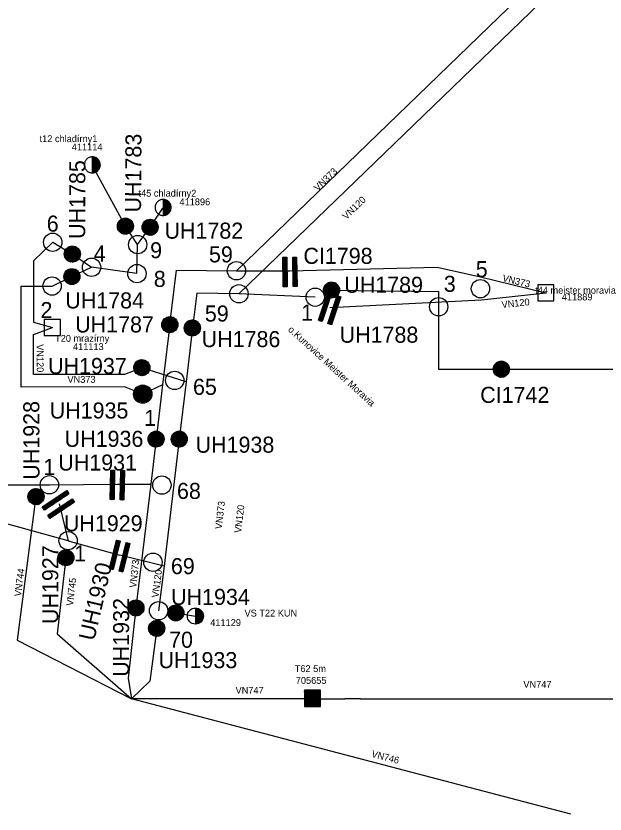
# Model space of a CAD drawing. Extents: x -541380 to -536551, y -1184364 to -1179471.
# Drawn here: x -540352 to -539067, y -1184364 to -1182623 of the extents above; entities that cross this region are included whole.
import ezdxf

# ---------------------------------------------------------------- set-up
doc = ezdxf.new("R2010")
doc.units = 0
for name, color, linetype in [('Default', 7, 'Continuous'), ('Vrstva 1', 7, 'Continuous'), ('Vrstva 2', 7, 'Continuous'), ('Vrstva 20', 7, 'Continuous'), ('Vrstva 3', 7, 'Continuous'), ('Vrstva 5', 7, 'Continuous')]:
    doc.layers.add(name, color=color, linetype=linetype)

# ---------------------------------------------------------------- blocks, each defined once
blk = doc.blocks.new('PS100')
at = {"layer": 'Default'}
for p, q in [((-17.5, -0.7), (0.7, 17.5)), ((-17.5, 0.7), (-0.7, 17.5)), ((-17.4, -2), (2, 17.4)), ((-17.3, 2.2), (-2.2, 17.3)), ((-17.2, -3.3), (3.3, 17.2)), ((-17, 4), (-4, 17)), ((-16.9, -4.4), (4.4, 16.9)), ((-16.6, -5.5), (5.5, 16.6)), ((-16.4, 6), (-6, 16.4)), ((-16.2, -6.5), (6.5, 16.2)), ((-15.8, -7.5), (7.5, 15.8)), ((-15.3, -8.4), (8.4, 15.3)), ((-15.2, 8.6), (-8.6, 15.2)), ((-14.8, -9.3), (9.3, 14.8)), ((-14.2, -10.2), (10.2, 14.2)), ((-13.6, -11), (11, 13.6)), ((-13, -11.7), (11.7, 13)), ((-12.3, -12.5), (12.5, 12.3)), ((-11.5, -13.2), (13.2, 11.5)), ((-10.8, -13.8), (13.8, 10.8)), ((-9.9, -14.4), (14.4, 9.9)), ((-9.1, -14.9), (14.9, 9.1)), ((-8.2, -15.5), (15.5, 8.2)), ((-7.2, -15.9), (15.9, 7.2)), ((-6.2, -16.3), (16.3, 6.2)), ((-5.2, -16.7), (16.7, 5.2)), ((-4.1, -17), (17, 4.1)), ((-2.9, -17.2), (17.2, 2.9)), ((-1.6, -17.4), (17.4, 1.6)), ((-0.3, -17.5), (17.5, 0.3)), ((1.1, -17.4), (17.4, -1.1)), ((2.7, -17.3), (17.3, -2.7)), ((4.5, -16.9), (16.9, -4.5)), ((6.7, -16.2), (16.2, -6.7)), ((9.7, -14.5), (14.5, -9.7))]:
    blk.add_line(p, q, dxfattribs=at)
blk.add_circle((0, 0), 17.5, dxfattribs=at)
blk = doc.blocks.new('PS140')
at = {"layer": 'Default'}
for p, q in [((-17.5, 0), (0, 17.5)), ((-17.4, -1.4), (1.4, 17.4)), ((-17.4, 1.5), (-1.5, 17.4)), ((-17.3, -2.6), (2.6, 17.3)), ((-17.2, 3.1), (-3.1, 17.2)), ((-17.1, -3.8), (3.8, 17.1)), ((-16.8, -4.9), (4.9, 16.8)), ((-16.8, 5), (-5, 16.8)), ((-16.4, -6), (6, 16.4)), ((-16, -7), (7, 16)), ((-15.9, 7.2), (-7.2, 15.9)), ((-15.6, -8), (8, 15.6)), ((-15.1, -8.9), (8.9, 15.1)), ((-14.5, -9.8), (9.8, 14.5)), ((-13.9, -10.6), (10.6, 13.9)), ((-13.8, 10.8), (-10.8, 13.8)), ((-13.3, -11.4), (11.4, 13.3)), ((-12.6, -12.1), (12.1, 12.6)), ((-11.9, -12.8), (12.8, 11.9)), ((-11.2, -13.5), (13.5, 11.2)), ((-10.4, -14.1), (14.1, 10.4)), ((-9.5, -14.7), (14.7, 9.5)), ((-8.6, -15.2), (15.2, 8.6)), ((-7.7, -15.7), (15.7, 7.7)), ((-6.7, -16.1), (16.1, 6.7)), ((-5.7, -16.5), (16.5, 5.7)), ((-4.6, -16.9), (16.9, 4.6)), ((-3.5, -17.1), (17.1, 3.5)), ((-2.3, -17.3), (17.3, 2.3)), ((-1, -17.5), (17.5, 1)), ((0.4, -17.5), (17.5, -0.4)), ((1.9, -17.4), (17.4, -1.9)), ((3.6, -17.1), (17.1, -3.6)), ((5.5, -16.6), (16.6, -5.5)), ((8, -15.6), (15.6, -8))]:
    blk.add_line(p, q, dxfattribs=at)
blk.add_circle((0, 0), 17.5, dxfattribs=at)
blk = doc.blocks.new('PS150')
at = {"layer": 'Default'}
for p, q in [((-15.1, 22.4), (-7.4, 30.1)), ((-15.1, 23.8), (-8.8, 30.1)), ((-15.1, 25.2), (-10.2, 30.1)), ((-15.1, 26.6), (-11.6, 30.1)), ((-15.1, 28), (-13, 30.1)), ((-15.1, 29.4), (-14.4, 30.1)), ((-15.1, 20.9), (-6.5, 29.5)), ((-15.1, 19.5), (-6.5, 28.1)), ((-15.1, 18.1), (-6.5, 26.7)), ((-15.1, 16.7), (-6.5, 25.3)), ((-15.1, 15.3), (-6.5, 23.9)), ((-15.1, 13.9), (-6.5, 22.4)), ((-15.1, 12.5), (-6.5, 21)), ((-15.1, 11), (-6.5, 19.6)), ((-15.1, 9.6), (-6.5, 18.2)), ((6.7, 22.6), (14.1, 30.1)), ((6.7, 24), (12.7, 30.1)), ((6.7, 25.4), (11.3, 30.1)), ((6.7, 26.8), (9.9, 30.1)), ((6.7, 28.3), (8.5, 30.1)), ((6.7, 29.7), (7, 30.1)), ((6.7, 21.2), (15.2, 29.8)), ((6.7, 19.8), (15.2, 28.3)), ((6.7, 18.4), (15.2, 26.9)), ((6.7, 16.9), (15.2, 25.5)), ((6.7, 15.5), (15.2, 24.1)), ((6.7, 14.1), (15.2, 22.7)), ((6.7, 12.7), (15.2, 21.3)), ((6.7, 11.3), (15.2, 19.9)), ((6.7, 9.9), (15.2, 18.4)), ((-15.1, 8.2), (-6.5, 16.8)), ((-15.1, 6.8), (-6.5, 15.4)), ((-15.1, 5.4), (-6.5, 14)), ((-15.1, 4), (-6.5, 12.5)), ((-15.1, 2.6), (-6.5, 11.1)), ((-15.1, 1.2), (-6.5, 9.7)), ((-15.1, -0.3), (-6.5, 8.3)), ((-15.1, -1.7), (-6.5, 6.9)), ((-15.1, -3.1), (-6.5, 5.5)), ((-15.1, -4.5), (-6.5, 4.1)), ((-15.1, -5.9), (-6.5, 2.6)), ((-15.1, -7.3), (-6.5, 1.2)), ((6.7, 8.5), (15.2, 17)), ((6.7, 7.1), (15.2, 15.6)), ((6.7, 5.6), (15.2, 14.2)), ((6.7, 4.2), (15.2, 12.8)), ((6.7, 2.8), (15.2, 11.4)), ((6.7, 1.4), (15.2, 10)), ((6.7, 0), (15.2, 8.5)), ((6.7, -1.4), (15.2, 7.1)), ((6.7, -2.8), (15.2, 5.7)), ((6.7, -4.3), (15.2, 4.3)), ((6.7, -5.7), (15.2, 2.9)), ((6.7, -7.1), (15.2, 1.5)), ((6.7, -8.5), (15.2, 0.1)), ((-15.1, -8.7), (-6.5, -0.2)), ((-15.1, -10.2), (-6.5, -1.6)), ((-15.1, -11.6), (-6.5, -3)), ((-15.1, -13), (-6.5, -4.4)), ((-15.1, -14.4), (-6.5, -5.8)), ((-15.1, -15.8), (-6.5, -7.3)), ((-15.1, -17.2), (-6.5, -8.7)), ((-15.1, -18.6), (-6.5, -10.1)), ((-15.1, -20.1), (-6.5, -11.5)), ((-15.1, -21.5), (-6.5, -12.9)), ((-15.1, -22.9), (-6.5, -14.3)), ((-15.1, -24.3), (-6.5, -15.7)), ((-15.1, -25.7), (-6.5, -17.2)), ((6.7, -9.9), (15.2, -1.4)), ((6.7, -11.3), (15.2, -2.8)), ((6.7, -12.7), (15.2, -4.2)), ((6.7, -14.2), (15.2, -5.6)), ((6.7, -15.6), (15.2, -7)), ((6.7, -17), (15.2, -8.4)), ((6.7, -18.4), (15.2, -9.8)), ((6.7, -19.8), (15.2, -11.3)), ((6.7, -21.2), (15.2, -12.7)), ((6.7, -22.6), (15.2, -14.1)), ((6.7, -24.1), (15.2, -15.5)), ((6.7, -25.5), (15.2, -16.9)), ((-15.1, -27.1), (-6.5, -18.6)), ((-15.1, -28.5), (-6.5, -20)), ((-15.1, -30), (-6.5, -21.4)), ((-15.1, -31.4), (-6.5, -22.8)), ((-15.1, -32.8), (-6.5, -24.2)), ((-15, -34.2), (-6.5, -25.6)), ((-13.6, -34.2), (-6.5, -27.1)), ((-12.2, -34.2), (-6.5, -28.5)), ((-10.8, -34.2), (-6.5, -29.9)), ((-9.4, -34.2), (-6.5, -31.3)), ((-8, -34.2), (-6.5, -32.7)), ((-6.5, -34.2), (-6.5, -34.1)), ((6.7, -26.9), (15.2, -18.3)), ((6.7, -28.3), (15.2, -19.7)), ((6.7, -29.7), (15.2, -21.2)), ((6.7, -31.1), (15.2, -22.6)), ((6.7, -32.5), (15.2, -24)), ((6.7, -34), (15.2, -25.4)), ((7.9, -34.2), (15.2, -26.8)), ((9.3, -34.2), (15.2, -28.2)), ((10.7, -34.2), (15.2, -29.6)), ((12.1, -34.2), (15.2, -31)), ((13.5, -34.2), (15.2, -32.5)), ((14.9, -34.2), (15.2, -33.9))]:
    blk.add_line(p, q, dxfattribs=at)
for points in [[(-6.5, 30.1), (-6.5, -34.2), (-15.1, -34.2), (-15.1, 30.1)], [(15.2, 30.1), (15.2, -34.2), (6.7, -34.2), (6.7, 30.1)]]:
    blk.add_lwpolyline(points, close=True, dxfattribs=at)
blk = doc.blocks.new('PS610')
at = {"layer": 'Default'}
for p, q in [((0, 16.2), (1.3, 17.4)), ((0, 14.7), (2.5, 17.3)), ((0, 13.3), (3.7, 17.1)), ((0, 11.9), (4.9, 16.8)), ((0, 10.5), (5.9, 16.4)), ((0, 9.1), (7, 16)), ((0, 7.7), (7.9, 15.6)), ((0, 6.3), (8.8, 15.1)), ((0, 4.8), (9.7, 14.5)), ((0, 3.4), (10.5, 14)), ((0, 2), (11.3, 13.3)), ((0, 0.6), (12, 12.7)), ((0, -0.8), (12.8, 12)), ((0, -2.2), (13.4, 11.2)), ((0, -3.6), (14, 10.4)), ((0, -5), (14.6, 9.6)), ((0, -6.5), (15.2, 8.7)), ((0, -7.9), (15.6, 7.8)), ((0, -9.3), (16.1, 6.8)), ((0, -10.7), (16.5, 5.8)), ((0, -12.1), (16.8, 4.7)), ((0, -13.5), (17.1, 3.6)), ((0, -14.9), (17.3, 2.4)), ((0, -16.4), (17.4, 1.1)), ((0.3, -17.5), (17.5, -0.3)), ((1.8, -17.4), (17.4, -1.8)), ((3.5, -17.1), (17.1, -3.5)), ((5.4, -16.7), (16.7, -5.4)), ((7.8, -15.7), (15.6, -7.8))]:
    blk.add_line(p, q, dxfattribs=at)
blk.add_lwpolyline([(0, 17.5), (0, -17.5)], dxfattribs=at)
blk.add_circle((0, 0), 17.5, dxfattribs=at)
blk = doc.blocks.new('PS800')
at = {"layer": 'Vrstva 2'}
blk.add_circle((0, 0), 20, dxfattribs=at)
blk = doc.blocks.new('PS650')
at = {"layer": 'Vrstva 20'}
for points in [[(17.5, 17.5), (-17.5, 17.5)], [(-17.5, 17.5), (-17.5, -17.5)], [(17.5, -17.5), (17.5, 17.5)], [(-17.5, -17.5), (17.5, -17.5)]]:
    blk.add_lwpolyline(points, dxfattribs=at)
blk = doc.blocks.new('PS630')
at = {"layer": 'Default'}
for p, q in [((-16.6, -14.9), (17.1, 18.7)), ((-16.6, -13.5), (15.7, 18.7)), ((-16.6, -12.1), (14.2, 18.7)), ((-16.6, -10.7), (12.8, 18.7)), ((-16.6, -9.3), (11.4, 18.7)), ((-16.6, -7.9), (10, 18.7)), ((-16.6, -6.5), (8.6, 18.7)), ((-16.6, -5), (7.2, 18.7)), ((-16.6, -3.6), (5.8, 18.7)), ((-16.6, -2.2), (4.3, 18.7)), ((-16.6, -0.8), (2.9, 18.7)), ((-16.6, 0.6), (1.5, 18.7)), ((-16.6, 2), (0.1, 18.7)), ((-16.6, 3.4), (-1.3, 18.7)), ((-16.6, 4.9), (-2.7, 18.7)), ((-16.6, 6.3), (-4.1, 18.7)), ((-16.6, 7.7), (-5.6, 18.7)), ((-16.6, 9.1), (-7, 18.7)), ((-16.6, 10.5), (-8.4, 18.7)), ((-16.6, 11.9), (-9.8, 18.7)), ((-16.6, 13.3), (-11.2, 18.7)), ((-16.6, 14.8), (-12.6, 18.7)), ((-16.6, 16.2), (-14, 18.7)), ((-16.6, 17.6), (-15.5, 18.7)), ((-16.5, -16.3), (18.4, 18.6)), ((-15.1, -16.3), (18.4, 17.2)), ((-13.7, -16.3), (18.4, 15.8)), ((-12.3, -16.3), (18.4, 14.4)), ((-10.9, -16.3), (18.4, 13)), ((-9.4, -16.3), (18.4, 11.6)), ((-8, -16.3), (18.4, 10.2)), ((-6.6, -16.3), (18.4, 8.7)), ((-5.2, -16.3), (18.4, 7.3)), ((-3.8, -16.3), (18.4, 5.9)), ((-2.4, -16.3), (18.4, 4.5)), ((-1, -16.3), (18.4, 3.1)), ((0.5, -16.3), (18.4, 1.7)), ((1.9, -16.3), (18.4, 0.3)), ((3.3, -16.3), (18.4, -1.2)), ((4.7, -16.3), (18.4, -2.6)), ((6.1, -16.3), (18.4, -4)), ((7.5, -16.3), (18.4, -5.4)), ((8.9, -16.3), (18.4, -6.8)), ((10.4, -16.3), (18.4, -8.2)), ((11.8, -16.3), (18.4, -9.6)), ((13.2, -16.3), (18.4, -11.1)), ((14.6, -16.3), (18.4, -12.5)), ((16, -16.3), (18.4, -13.9)), ((17.4, -16.3), (18.4, -15.3))]:
    blk.add_line(p, q, dxfattribs=at)
for points in [[(-16.6, 18.7), (-16.6, -16.3)], [(18.4, 18.7), (-16.6, 18.7)], [(-16.6, 18.7), (-16.6, -16.3)], [(18.4, -16.3), (18.4, 18.7)], [(-16.6, -16.3), (18.4, -16.3)]]:
    blk.add_lwpolyline(points, dxfattribs=at)
blk = doc.blocks.new('PS611')
at = {"layer": 'Default'}
for p, q in [((0, 16.2), (1.3, 17.4)), ((0, 14.7), (2.5, 17.3)), ((0, 13.3), (3.7, 17.1)), ((0, 11.9), (4.9, 16.8)), ((0, 10.5), (5.9, 16.4)), ((0, 9.1), (7, 16)), ((0, 7.7), (7.9, 15.6)), ((0, 6.3), (8.8, 15.1)), ((0, 4.8), (9.7, 14.5)), ((0, 3.4), (10.5, 14)), ((0, 2), (11.3, 13.3)), ((0, 0.6), (12, 12.7)), ((0, -0.8), (12.8, 12)), ((0, -2.2), (13.4, 11.2)), ((0, -3.6), (14, 10.4)), ((0, -5), (14.6, 9.6)), ((0, -6.5), (15.2, 8.7)), ((0, -7.9), (15.6, 7.8)), ((0, -9.3), (16.1, 6.8)), ((0, -10.7), (16.5, 5.8)), ((0, -12.1), (16.8, 4.7)), ((0, -13.5), (17.1, 3.6)), ((0, -14.9), (17.3, 2.4)), ((0, -16.4), (17.4, 1.1)), ((0.3, -17.5), (17.5, -0.3)), ((1.8, -17.4), (17.4, -1.8)), ((3.5, -17.1), (17.1, -3.5)), ((5.4, -16.7), (16.7, -5.4)), ((7.8, -15.7), (15.6, -7.8))]:
    blk.add_line(p, q, dxfattribs=at)
for points in [[(17.5, 0), (17.4, 1.8), (17.1, 3.6), (16.6, 5.4), (16, 7.1), (15.2, 8.8), (14.2, 10.3), (13, 11.7), (11.7, 13), (10.3, 14.2), (8.7, 15.2), (7.1, 16), (5.4, 16.6), (3.6, 17.1), (1.8, 17.4), (0, 17.5), (-1.8, 17.4), (-3.6, 17.1), (-5.4, 16.6), (-7.1, 16), (-8.8, 15.2), (-10.3, 14.2), (-11.7, 13), (-13, 11.7), (-14.2, 10.3), (-15.2, 8.7), (-16, 7.1), (-16.6, 5.4), (-17.1, 3.6), (-17.4, 1.8), (-17.5, 0), (-17.4, -1.8), (-17.1, -3.6), (-16.6, -5.4), (-16, -7.1), (-15.2, -8.8), (-14.2, -10.3), (-13, -11.7), (-11.7, -13), (-10.3, -14.2), (-8.8, -15.2), (-7.1, -16), (-5.4, -16.6), (-3.6, -17.1), (-1.8, -17.4), (0, -17.5), (1.8, -17.4), (3.6, -17.1), (5.4, -16.6), (7.1, -16), (8.8, -15.2), (10.3, -14.2), (11.7, -13), (13, -11.7), (14.2, -10.3), (15.2, -8.8), (16, -7.1), (16.6, -5.4), (17.1, -3.6), (17.4, -1.8), (17.5, 0)], [(0, 17.5), (0, -17.5)]]:
    blk.add_lwpolyline(points, dxfattribs=at)
blk = doc.blocks.new('PS651')
at = {"layer": 'Vrstva 20'}
for points in [[(17.5, 17.5), (-17.5, 17.5)], [(-17.5, 17.5), (-17.5, -17.5)], [(17.5, -17.5), (17.5, 17.5)], [(-17.5, -17.5), (17.5, -17.5)]]:
    blk.add_lwpolyline(points, dxfattribs=at)

msp = doc.modelspace()

# ---------------------------------------------------------------- linework, layer by layer
at = {"layer": 'Vrstva 1'}
for points in [[(-538730.2, -1181781.1), (-538745.8, -1181888.8), (-538896.2, -1182293.4), (-539271.4, -1182655.8), (-539865.4, -1183229.4)], [(-539298.4, -1182626.3), (-539078.2, -1182413.6)], [(-539870.7, -1183179.1), (-539298.4, -1182626.3)], [(-540113.1, -1183082), (-540184.9, -1182950.2)], [(-540059.1, -1183084.2), (-540031.4, -1183042.7)], [(-540086.3, -1183122.1), (-540113.1, -1183082)], [(-540086.3, -1183122.1), (-540059.1, -1183084.2)], [(-540313.8, -1183157.6), (-540271.5, -1183117.1)], [(-540271.5, -1183117.1), (-540228.8, -1183142.7)], [(-540087.9, -1183185.4), (-540086.3, -1183122.1)], [(-540228.8, -1183142.7), (-540186.9, -1183171.6)], [(-540313.8, -1183157.6), (-540313.8, -1183291.1), (-540272.4, -1183302.6)], [(-540229.7, -1183191.8), (-540186.9, -1183171.6)], [(-540135.2, -1183178.8), (-540186.9, -1183171.6)], [(-540087.9, -1183185.4), (-540135.2, -1183178.8)], [(-540016.1, -1183296.7), (-540001.7, -1183177.6), (-539870.7, -1183179.1)], [(-539870.7, -1183179.1), (-539754.1, -1183179.6)], [(-539754.1, -1183179.6), (-539433, -1183171.4), (-539338.5, -1183192.6)], [(-540272.9, -1183212.5), (-540229.7, -1183191.8)], [(-539338.5, -1183192.6), (-539196, -1183227.4)], [(-540075.3, -1183448.2), (-540115.1, -1183432.6), (-540340.7, -1183432.8), (-540340.6, -1183212.5), (-540272.9, -1183212.5)], [(-539663.2, -1183221.2), (-539429.6, -1183224.5), (-539429.6, -1183393.8), (-539292.9, -1183393.8)], [(-539865.4, -1183229.4), (-539957.4, -1183228.3), (-539967, -1183303.9)], [(-539699, -1183236.8), (-539865.4, -1183229.4), (-539865.4, -1183229.4)], [(-539335.9, -1183242.5), (-539196, -1183227.4)], [(-539666.8, -1183259.6), (-539335.9, -1183242.5)], [(-540077.1, -1183390.5), (-540115.2, -1183405.7), (-540313.4, -1183405.6), (-540313.4, -1183318), (-540272.4, -1183302.6)], [(-540016.1, -1183296.7), (-540032.2, -1183427.6)], [(-539967, -1183303.9), (-539980.5, -1183421.3)], [(-539980.5, -1183421.3), (-540077.1, -1183390.5)], [(-539292.9, -1183393.8), (-539166.7, -1183393.8)], [(-539166.7, -1183393.8), (-539032.6, -1183393.8)], [(-540032.1, -1183427.6), (-540075.3, -1183448.2)], [(-540032.1, -1183427.6), (-540046, -1183546.3)], [(-539980.5, -1183421.3), (-539995.6, -1183546.3)], [(-540046, -1183546.3), (-540057.8, -1183644.9)], [(-539995.6, -1183546.3), (-540028.8, -1183823.3)], [(-540238, -1183767.8), (-540417.2, -1183718.4), (-540591.8, -1183607), (-541124.4, -1183583.7)], [(-540470.7, -1183594.2), (-540396.7, -1183646.3), (-540278.9, -1183646)], [(-540278.9, -1183646), (-540130.6, -1183644.3)], [(-540130.6, -1183644.3), (-540057.8, -1183644.9)], [(-540057.8, -1183644.9), (-540090, -1183914.6)], [(-540308.1, -1183671.6), (-540349.2, -1183984.9), (-540100, -1184112.8)], [(-540257.8, -1183687.7), (-540238, -1183767.8)], [(-540238, -1183767.8), (-540125.1, -1183799.2)], [(-540242.9, -1183805.1), (-540262.2, -1183971.2), (-540100, -1184112.8)], [(-540028.8, -1183823.3), (-540125.1, -1183799.2)], [(-540028.8, -1183823.3), (-540040.5, -1183920.6)], [(-540090, -1183914.6), (-540107, -1184067.6), (-540100, -1184112.8)], [(-540002.9, -1183925.4), (-539960.4, -1183932.2)], [(-540044.8, -1183959), (-540059.8, -1184073.9), (-540100, -1184112.8)], [(-539141.5, -1184364), (-540100, -1184112.8)], [(-539724.5, -1184112.8), (-540100, -1184112.8)], [(-539705.8, -1184112.8), (-539724.5, -1184112.8)], [(-539705.8, -1184112.8), (-539634.1, -1184112.6)], [(-539600, -1184112.8), (-539634.1, -1184112.6)], [(-539600, -1184112.8), (-538830.3, -1184112.8)]]:
    msp.add_lwpolyline(points, dxfattribs=at)

# ---------------------------------------------------------------- block references
at = {"layer": 'Vrstva 2'}
for name, p, rotation in [('PS140', (-540113.1, -1183082), 107.19590279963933), ('PS140', (-540059.1, -1183084.2), -66.5734055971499), ('PS140', (-540228.8, -1183142.7), -28.299599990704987), ('PS150', (-539754.1, -1183179.6), 1.0974722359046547), ('PS140', (-540229.7, -1183191.8), -137.72051106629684), ('PS140', (-539663.2, -1183221.2), 43.89927496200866), ('PS150', (-539666.8, -1183259.6), -18.630803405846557), ('PS140', (-540016.1, -1183296.7), 84.6160527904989), ('PS140', (-539967, -1183303.9), 81.48321110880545), ('PS140', (-540077.1, -1183390.5), 7.688058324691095), ('PS140', (-539292.9, -1183393.8), -6.948050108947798), ('PS140', (-540075.3, -1183448.2), 59.104705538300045), ('PS140', (-540046, -1183546.3), 82.97227774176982), ('PS140', (-539995.6, -1183546.3), -96.68660837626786), ('PS150', (-540130.6, -1183644.3), -1.1817719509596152), ('PS140', (-540308.1, -1183671.6), -5.999733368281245), ('PS150', (-540257.8, -1183687.7), -56.342046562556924), ('PS150', (-540125.1, -1183799.2), -13.995237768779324), ('PS100', (-540242.9, -1183805.1), -153.43188052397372), ('PS140', (-540090, -1183914.6), 70.46426947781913), ('PS140', (-540002.9, -1183925.4), -94.40686662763), ('PS140', (-540044.8, -1183959), -61.5249416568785)]:
    msp.add_blockref(name, p, dxfattribs=dict(at, rotation=rotation))
at = {"layer": 'Vrstva 3'}
for name, p in [('PS611', (-540185.2, -1182948.3)), ('PS611', (-540030.7, -1183041)), ('PS651', (-539196, -1183227.4)), ('PS650', (-540272.4, -1183302.6)), ('PS610', (-539960.4, -1183932.2)), ('PS630', (-539705.8, -1184112.8))]:
    msp.add_blockref(name, p, dxfattribs=at)
at = {"layer": 'Vrstva 5'}
for p, rotation in [((-540271.5, -1183117.1), 81.87711381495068), ((-540086.3, -1183122.1), -14.150816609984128), ((-540186.9, -1183171.6), 79.52871106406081), ((-540087.9, -1183185.4), -10.367486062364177), ((-539870.7, -1183179.1), 5.629222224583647), ((-540272.9, -1183212.5), -78.54001944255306), ((-539338.4, -1183218.3), 4.80739434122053), ((-539865.4, -1183229.4), 5.814858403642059), ((-539699, -1183236.8), 5.99906389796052), ((-539429.6, -1183257.6), -14.14605001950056), ((-540005.5, -1183418.3), 84.0429694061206), ((-540075.3, -1183448.2), -70.16778056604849), ((-540075.3, -1183448.2), -93.51351665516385), ((-540278.9, -1183646), -7.290502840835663), ((-540033.5, -1183646.6), -9.78719996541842), ((-540238, -1183767.8), -24.336652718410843), ((-540052.9, -1183814.9), -19.91056951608)]:
    msp.add_blockref('PS800', p, dxfattribs=dict(at, rotation=rotation))
msp.add_blockref('PS800', (-540040.5, -1183920.6), dxfattribs=at)

# ---------------------------------------------------------------- texts
at = {"layer": 'Vrstva 1'}
for s, rotation, p in [('VN373', 44.008, (-539693.3, -1183006.6)), ('VN120', 44, (-539631.1, -1183068.6)), ('VN373', 346.262, (-539291.6, -1183201.6)), ('VN120', 6.155, (-539291.5, -1183260.7)), ('o.Kunovice Meister Moravia', 317.59, (-539759.5, -1183309.2)), ('VN120', 270.233, (-540306.6, -1183339.2)), ('VN373', 0.039, (-540239.4, -1183423.5)), ('VN373', 83.207, (-539902.9, -1183743.4)), ('VN120', 83.174, (-539860.6, -1183751.6)), ('VN373', 83.635, (-540089.5, -1183871.2)), ('VN744', 82.523, (-540340.8, -1183890.2)), ('VN120', 82.563, (-540040.9, -1183892.7)), ('VN745', 83.382, (-540227.2, -1183910.6)), ('VN746', 345.317, (-539577.3, -1184239.2))]:
    msp.add_text(s, height=15, rotation=rotation, dxfattribs=at).set_placement(p)
for p in [(-539244.8, -1184088.7), (-539872.7, -1184101.6)]:
    msp.add_text('VN747', height=15, dxfattribs=at).set_placement(p)
at = {"layer": 'Vrstva 2'}
for s, rotation, p in [('UH1783', 89.628, (-540079, -1183052.1)), ('UH1785', 89.849, (-540200.9, -1183109.8)), ('UH1928', 90.175, (-540300.4, -1183634.8)), ('UH1927', 90, (-540259.4, -1183949.6)), ('UH1930', 76.851, (-540181.2, -1183987.8)), ('UH1932', 90, (-540104.9, -1184064.7))]:
    msp.add_text(s, height=35, rotation=rotation, dxfattribs=at).set_placement(p)
for s, p in [('UH1782', (-540027.7, -1183109.2)), ('CI1798', (-539724.7, -1183164.1)), ('UH1789', (-539635.5, -1183227.2)), ('UH1784', (-540244.2, -1183261.3)), ('UH1787', (-540222.6, -1183313.7)), ('UH1788', (-539645.7, -1183336.1)), ('UH1786', (-539946.7, -1183345.7)), ('UH1937', (-540281.7, -1183404.3)), ('CI1742', (-539339, -1183467.3)), ('UH1935', (-540278.2, -1183501.4)), ('UH1936', (-540245.6, -1183563.2)), ('UH1938', (-539959.9, -1183576)), ('UH1931', (-540259.4, -1183614.9)), ('UH1929', (-540247.2, -1183747.4)), ('UH1934', (-540013.3, -1183907.9)), ('UH1933', (-540040.7, -1184045.8))]:
    msp.add_text(s, height=35, dxfattribs=at).set_placement(p)
at = {"layer": 'Vrstva 3'}
for s, p in [('t12 chladírny1', (-540300.2, -1182898.6)), ('411114', (-540230, -1182916.8)), ('t45 chladírny2', (-540084.4, -1183017.5)), ('411896', (-539995, -1183036.3)), ('t44 meister moravia', (-539219.1, -1183229.2)), ('411889', (-539160.9, -1183243.8)), ('T20 mrazírny', (-540266.4, -1183334.1)), ('411113', (-540227.4, -1183352.1)), ('VS T22 KUN', (-539853.1, -1183933.2)), ('411129', (-539927.9, -1183954)), ('T62 5m', (-539743.5, -1184054.4)), ('705655', (-539741.3, -1184080))]:
    msp.add_text(s, height=15, dxfattribs=at).set_placement(p)
at = {"layer": 'Vrstva 5'}
for s, p in [('6', (-540284.6, -1183093.8)), ('9', (-540059.1, -1183151.9)), ('4', (-540182.2, -1183159)), ('59', (-539930.7, -1183160.9)), ('5', (-539348.6, -1183193.2)), ('8', (-540051.1, -1183214.4)), ('3', (-539418.3, -1183225.1)), ('2', (-540298.3, -1183282.4)), ('59', (-539939.7, -1183289.9)), ('1', (-539729.7, -1183287.8)), ('65', (-539965.6, -1183449.8)), ('1', (-540072.1, -1183517.5)), ('1', (-540292.1, -1183624.4)), ('68', (-540000.5, -1183676.8)), ('1', (-540224.8, -1183813.1)), ('69', (-540013.8, -1183840.8)), ('70', (-540017.7, -1184001.3))]:
    msp.add_text(s, height=35, dxfattribs=at).set_placement(p)

doc.saveas('drawing.dxf')
